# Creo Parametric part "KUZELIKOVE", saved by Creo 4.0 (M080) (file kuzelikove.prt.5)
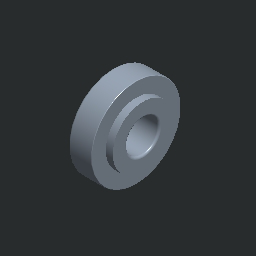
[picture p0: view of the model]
Units: Custom; MM, KILOGRAM, SECS
Materials in the file: OCEL_N

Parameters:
  MFG_WP_MATERIAL = "RO7"
  NAZOV = "KUZELIKOVE"
  PTC_MATERIAL_NAME = "OCEL_N"

Other parameters: HMOTNOST, HUSTOTA, D3, D1

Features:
  1. round
  2. round
  3. round

Named dimensions: Damin, velke_D

Layers: 1, 2, 3, 4, 5, 6, 7, 8, 9, 10, 11, 12, 13, 14, 15, 16, 17, 18, 19, 20, 21, 22, 23, 24, 25, 26, 27, 28, 29, 30, 31, 32

Family table entries: GENERIC, LOZISKO_30302A, KUZELIKOVE, value(d_val), 2/E, 2/*, 2/&, value(i_val), LOZISKO_30203A, KUZELIKOVE, !/1, 2/D, 2/(, 2/&, LOZISKO_30303A, KUZELIKOVE, !/1, 2/,, 2/(, LOZISKO_30204A, KUZELIKOVE, !/4, 2/,, 2/(, LOZISKO_30304A, KUZELIKOVE, !/4, 2/J, 2/., 2/*, LOZISKO_32304A, KUZELIKOVE, !/4, 2/J, 2/5, 2/2, LOZISKO_3205AX, KUZELIKOVE, !/9, 2/'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

Surfaces: 8 cylinder, 8 torus, 4 plane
